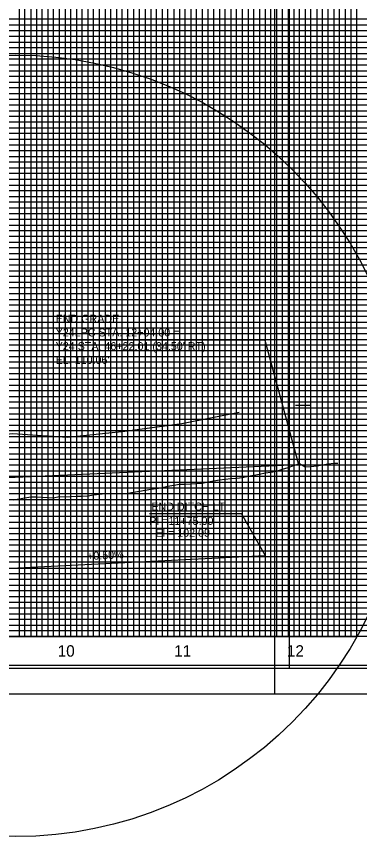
# Model space of a CAD drawing. Extents: x 2345490 to 2436403, y 465165 to 573888.
# Drawn here: x 2411853 to 2412153, y 523031 to 523748 of the extents above; entities that cross this region are included whole.
import ezdxf

# ---------------------------------------------------------------- set-up
doc = ezdxf.new("R2010")
doc.units = 0
for name, color, linetype in [('Old_Level_1', 7, 'Continuous'), ('Old_Level_18', 7, 'Continuous'), ('Old_Level_2', 7, 'Continuous'), ('Old_Level_3', 7, 'Continuous'), ('Old_Level_41', 7, 'Continuous'), ('Old_Level_42', 7, 'Continuous'), ('Old_Level_43', 7, 'Continuous'), ('Old_Level_50', 7, 'Continuous'), ('Old_Level_51', 7, 'Continuous'), ('Old_Level_52', 7, 'Continuous'), ('Old_Level_62', 7, 'Continuous'), ('Old_Level_63', 7, 'Continuous')]:
    doc.layers.add(name, color=color, linetype=linetype)

msp = doc.modelspace()

# ---------------------------------------------------------------- linework, layer by layer
at = {"layer": 'Old_Level_1'}
for points in [[(2411895.325, 523328.29225), (2411900.325, 523328.49575), (2411905.325, 523328.69875), (2411910.325, 523328.87125), (2411915.325, 523329.16725), (2411920.325, 523329.85425), (2411925.325, 523330.543), (2411930.325, 523331.213), (2411935.325, 523331.354), (2411940.325, 523331.2915), (2411945.325, 523331.228), (2411950.325, 523331.56175), (2411955.325, 523332.40075), (2411960.325, 523333.241), (2411965.325, 523334.03725), (2411970.325, 523334.8165), (2411975.325, 523335.638), (2411980.325, 523336.543), (2411985.325, 523337.448), (2411990.325, 523338.33525), (2411995.325, 523339.20225), (2412000.325, 523339.4425), (2412005.325, 523339.68275), (2412010.325, 523339.923), (2412015.325, 523340.271), (2412020.325, 523341.2105), (2412025.325, 523342.15), (2412030.325, 523343.073), (2412035.325, 523343.60075), (2412040.325, 523344.1285), (2412045.325, 523344.5875), (2412050.325, 523345.18675), (2412055.325, 523346.1825), (2412060.325, 523347.17825), (2412065.325, 523348.20575), (2412070.325, 523349.26625), (2412075.325, 523349.8425), (2412080.325, 523350.6675), (2412085.325, 523352.345), (2412090.325, 523354.02275), (2412095.325, 523355.70025), (2412100.325, 523357.37775), (2412105.325, 523354.34175), (2412110.325, 523354.80325), (2412115.325, 523355.2685), (2412120.325, 523356.19275), (2412125.325, 523357.16025), (2412130.325, 523357.7015), (2412133.825, 523357.63775)], [(2411850.325, 523325.50025), (2411855.325, 523326.38825), (2411860.325, 523327.27725), (2411865.325, 523328.109), (2411870.325, 523328.1615), (2411875.325, 523327.913), (2411880.325, 523327.676), (2411885.325, 523327.45375), (2411890.325, 523328.479), (2411895.325, 523328.29225)]]:
    msp.add_lwpolyline(points, dxfattribs=at)
at = {"layer": 'Old_Level_18'}
msp.add_lwpolyline([(2412345.325, 524230.9495), (2410845.325, 524230.9495), (2410845.325, 523180.9495), (2412345.325, 523180.9495)], close=True, dxfattribs=at)
at = {"layer": 'Old_Level_2'}
for p, q in [((2412069.99075, 523465.271), (2411874.5425, 523465.271)), ((2412069.99075, 523465.271), (2412099.325, 523356.5495)), ((2411845.325, 523345.0245), (2412099.325, 523356.5495))]:
    msp.add_line(p, q, dxfattribs=at)
at = {"layer": 'Old_Level_3'}
for p, q in [((2412049.63511, 523313.40272), (2411969.08786, 523313.40272)), ((2412049.63511, 523313.40272), (2412070.325, 523276.8495)), ((2411800.325, 523263.4495), (2412070.325, 523276.8495))]:
    msp.add_line(p, q, dxfattribs=at)
at = {"layer": 'Old_Level_41'}
for p, q in [((2412096.825, 523408.4495), (2412109.325, 523408.4495)), ((2412345.325, 523205.9495), (2410845.325, 523205.9495))]:
    msp.add_line(p, q, dxfattribs=at)
for points in [[(2411870.325, 524230.9495), (2411870.325, 523205.9495), (2411920.325, 523205.9495), (2411920.325, 524230.9495)], [(2411895.325, 524230.9495), (2411895.325, 523205.9495), (2411945.325, 523205.9495), (2411945.325, 524230.9495)], [(2411970.325, 524230.9495), (2411970.325, 523205.9495), (2412020.325, 523205.9495), (2412020.325, 524230.9495)], [(2411995.325, 524230.9495), (2411995.325, 523205.9495), (2412045.325, 523205.9495), (2412045.325, 524230.9495)], [(2412070.325, 524230.9495), (2412070.325, 523205.9495), (2412120.325, 523205.9495), (2412120.325, 524230.9495)], [(2412095.325, 524230.9495), (2412095.325, 523205.9495), (2412145.325, 523205.9495), (2412145.325, 524230.9495)], [(2412345.325, 523730.9495), (2410845.325, 523730.9495), (2410845.325, 523680.9495), (2412345.325, 523680.9495)], [(2412345.325, 523630.9495), (2410845.325, 523630.9495), (2410845.325, 523580.9495), (2412345.325, 523580.9495)], [(2412345.325, 523555.9495), (2410845.325, 523555.9495), (2410845.325, 523605.9495), (2412345.325, 523605.9495)], [(2412345.325, 523530.9495), (2410845.325, 523530.9495), (2410845.325, 523480.9495), (2412345.325, 523480.9495)], [(2412345.325, 523455.9495), (2410845.325, 523455.9495), (2410845.325, 523505.9495), (2412345.325, 523505.9495)], [(2412345.325, 523430.9495), (2410845.325, 523430.9495), (2410845.325, 523380.9495), (2412345.325, 523380.9495)], [(2412345.325, 523330.9495), (2410845.325, 523330.9495), (2410845.325, 523280.9495), (2412345.325, 523280.9495)], [(2412345.325, 523255.9495), (2410845.325, 523255.9495), (2410845.325, 523305.9495), (2412345.325, 523305.9495)], [(2412345.325, 523230.9495), (2410845.325, 523230.9495)]]:
    msp.add_lwpolyline(points, dxfattribs=at)
at = {"layer": 'Old_Level_42'}
for points in [[(2412345.325, 523655.9495), (2410845.325, 523655.9495), (2410845.325, 523705.9495), (2412345.325, 523705.9495)], [(2412345.325, 523355.9495), (2410845.325, 523355.9495), (2410845.325, 523405.9495), (2412345.325, 523405.9495)]]:
    msp.add_lwpolyline(points, dxfattribs=at)
at = {"layer": 'Old_Level_43'}
for points in [[(2411855.325, 524230.9495), (2411855.325, 523205.9495), (2411860.325, 523205.9495), (2411860.325, 524230.9495)], [(2411865.325, 524230.9495), (2411865.325, 523205.9495), (2411875.325, 523205.9495), (2411875.325, 524230.9495)], [(2411880.325, 524230.9495), (2411880.325, 523205.9495), (2411885.325, 523205.9495), (2411885.325, 524230.9495)], [(2411890.325, 524230.9495), (2411890.325, 523205.9495), (2411900.325, 523205.9495), (2411900.325, 524230.9495)], [(2411905.325, 524230.9495), (2411905.325, 523205.9495), (2411910.325, 523205.9495), (2411910.325, 524230.9495)], [(2411915.325, 524230.9495), (2411915.325, 523205.9495)], [(2411915.325, 523205.9495), (2411925.325, 523205.9495), (2411925.325, 524230.9495)], [(2411930.325, 524230.9495), (2411930.325, 523205.9495), (2411935.325, 523205.9495), (2411935.325, 524230.9495)], [(2411940.325, 524230.9495), (2411940.325, 523205.9495), (2411950.325, 523205.9495), (2411950.325, 524230.9495)], [(2411955.325, 524230.9495), (2411955.325, 523205.9495), (2411960.325, 523205.9495), (2411960.325, 524230.9495)], [(2411965.325, 524230.9495), (2411965.325, 523205.9495), (2411975.325, 523205.9495), (2411975.325, 524230.9495)], [(2411980.325, 524230.9495), (2411980.325, 523205.9495), (2411985.325, 523205.9495), (2411985.325, 524230.9495)], [(2411990.325, 524230.9495), (2411990.325, 523205.9495), (2412000.325, 523205.9495), (2412000.325, 524230.9495)], [(2412005.325, 524230.9495), (2412005.325, 523205.9495), (2412010.325, 523205.9495), (2412010.325, 524230.9495)], [(2412015.325, 524230.9495), (2412015.325, 523205.9495), (2412025.325, 523205.9495), (2412025.325, 524230.9495)], [(2412030.325, 524230.9495), (2412030.325, 523205.9495), (2412035.325, 523205.9495), (2412035.325, 524230.9495)], [(2412040.325, 524230.9495), (2412040.325, 523205.9495), (2412050.325, 523205.9495), (2412050.325, 524230.9495)], [(2412055.325, 524230.9495), (2412055.325, 523205.9495), (2412060.325, 523205.9495), (2412060.325, 524230.9495)], [(2412065.325, 524230.9495), (2412065.325, 523205.9495), (2412075.325, 523205.9495), (2412075.325, 524230.9495)], [(2412080.325, 524230.9495), (2412080.325, 523205.9495), (2412085.325, 523205.9495), (2412085.325, 524230.9495)], [(2412090.325, 524230.9495), (2412090.325, 523205.9495), (2412100.325, 523205.9495), (2412100.325, 524230.9495)], [(2412105.325, 524230.9495), (2412105.325, 523205.9495), (2412110.325, 523205.9495), (2412110.325, 524230.9495)], [(2412115.325, 524230.9495), (2412115.325, 523205.9495), (2412125.325, 523205.9495), (2412125.325, 524230.9495)], [(2412130.325, 524230.9495), (2412130.325, 523205.9495), (2412135.325, 523205.9495), (2412135.325, 524230.9495)], [(2412140.325, 524230.9495), (2412140.325, 523205.9495), (2412150.325, 523205.9495), (2412150.325, 524093.3995)], [(2412295.325, 523745.9495), (2410895.325, 523745.9495), (2410895.325, 523740.9495), (2412295.325, 523740.9495)], [(2412295.325, 523735.9495), (2410895.325, 523735.9495), (2410895.325, 523725.9495), (2412295.325, 523725.9495)], [(2412295.325, 523720.9495), (2410895.325, 523720.9495), (2410895.325, 523715.9495), (2412295.325, 523715.9495)], [(2412295.325, 523710.9495), (2410895.325, 523710.9495)], [(2410895.325, 523700.9495), (2412295.325, 523700.9495)], [(2412295.325, 523695.9495), (2410895.325, 523695.9495), (2410895.325, 523690.9495), (2412295.325, 523690.9495)], [(2412295.325, 523685.9495), (2410895.325, 523685.9495), (2410895.325, 523675.9495), (2412295.325, 523675.9495)], [(2412295.325, 523670.9495), (2410895.325, 523670.9495), (2410895.325, 523665.9495), (2412295.325, 523665.9495)], [(2412295.325, 523660.9495), (2410895.325, 523660.9495), (2410895.325, 523650.9495), (2412295.325, 523650.9495)], [(2412295.325, 523645.9495), (2410895.325, 523645.9495), (2410895.325, 523640.9495), (2412295.325, 523640.9495)], [(2412295.325, 523635.9495), (2410895.325, 523635.9495), (2410895.325, 523625.9495), (2412295.325, 523625.9495)], [(2412295.325, 523620.9495), (2410895.325, 523620.9495), (2410895.325, 523615.9495), (2412295.325, 523615.9495)], [(2412295.325, 523610.9495), (2410895.325, 523610.9495), (2410895.325, 523600.9495), (2412295.325, 523600.9495)], [(2412295.325, 523595.9495), (2410895.325, 523595.9495), (2410895.325, 523590.9495), (2412295.325, 523590.9495)], [(2412295.325, 523585.9495), (2410895.325, 523585.9495), (2410895.325, 523575.9495), (2412295.325, 523575.9495)], [(2412295.325, 523570.9495), (2410895.325, 523570.9495), (2410895.325, 523565.9495), (2412295.325, 523565.9495)], [(2412295.325, 523560.9495), (2410895.325, 523560.9495), (2410895.325, 523550.9495), (2412295.325, 523550.9495)], [(2412295.325, 523545.9495), (2410895.325, 523545.9495), (2410895.325, 523540.9495), (2412295.325, 523540.9495)], [(2412295.325, 523535.9495), (2410895.325, 523535.9495), (2410895.325, 523525.9495), (2412295.325, 523525.9495)], [(2412295.325, 523520.9495), (2410895.325, 523520.9495), (2410895.325, 523515.9495), (2412295.325, 523515.9495)], [(2412295.325, 523510.9495), (2410895.325, 523510.9495), (2410895.325, 523500.9495), (2412295.325, 523500.9495)], [(2412295.325, 523495.9495), (2410895.325, 523495.9495), (2410895.325, 523490.9495), (2412295.325, 523490.9495)], [(2412295.325, 523485.9495), (2410895.325, 523485.9495), (2410895.325, 523475.9495), (2412295.325, 523475.9495)], [(2412295.325, 523470.9495), (2410895.325, 523470.9495), (2410895.325, 523465.9495), (2412295.325, 523465.9495)], [(2412295.325, 523460.9495), (2410895.325, 523460.9495), (2410895.325, 523450.9495), (2412295.325, 523450.9495)], [(2412295.325, 523445.9495), (2410895.325, 523445.9495), (2410895.325, 523440.9495), (2412295.325, 523440.9495)], [(2412295.325, 523435.9495), (2410895.325, 523435.9495), (2410895.325, 523425.9495), (2412295.325, 523425.9495)], [(2412295.325, 523420.9495), (2410895.325, 523420.9495), (2410895.325, 523415.9495), (2412295.325, 523415.9495)], [(2412295.325, 523410.9495), (2410895.325, 523410.9495)], [(2410895.325, 523400.9495), (2412295.325, 523400.9495)], [(2412295.325, 523395.9495), (2410895.325, 523395.9495), (2410895.325, 523390.9495), (2412295.325, 523390.9495)], [(2412295.325, 523385.9495), (2410895.325, 523385.9495)], [(2410895.325, 523375.9495), (2412295.325, 523375.9495)], [(2412295.325, 523370.9495), (2410895.325, 523370.9495), (2410895.325, 523365.9495), (2412295.325, 523365.9495)], [(2412295.325, 523360.9495), (2410895.325, 523360.9495), (2410895.325, 523350.9495), (2412295.325, 523350.9495)], [(2412295.325, 523345.9495), (2410895.325, 523345.9495), (2410895.325, 523340.9495), (2412295.325, 523340.9495)], [(2412295.325, 523335.9495), (2410895.325, 523335.9495), (2410895.325, 523325.9495), (2412295.325, 523325.9495)], [(2412295.325, 523320.9495), (2410895.325, 523320.9495), (2410895.325, 523315.9495), (2412295.325, 523315.9495)], [(2412295.325, 523310.9495), (2410895.325, 523310.9495), (2410895.325, 523300.9495), (2412295.325, 523300.9495)], [(2412295.325, 523295.9495), (2410895.325, 523295.9495), (2410895.325, 523290.9495), (2412295.325, 523290.9495)], [(2412295.325, 523285.9495), (2410895.325, 523285.9495), (2410895.325, 523275.9495), (2412295.325, 523275.9495)], [(2412295.325, 523270.9495), (2410895.325, 523270.9495), (2410895.325, 523265.9495), (2412295.325, 523265.9495)], [(2412295.325, 523260.9495), (2410895.325, 523260.9495), (2410895.325, 523250.9495), (2412295.325, 523250.9495)], [(2412295.325, 523245.9495), (2410895.325, 523245.9495), (2410895.325, 523240.9495), (2412295.325, 523240.9495)], [(2412295.325, 523235.9495), (2410895.325, 523235.9495), (2410895.325, 523225.9495), (2412295.325, 523225.9495)], [(2412295.325, 523220.9495), (2410895.325, 523220.9495), (2410895.325, 523215.9495), (2412295.325, 523215.9495)], [(2412295.325, 523210.9495), (2410895.325, 523210.9495)]]:
    msp.add_lwpolyline(points, dxfattribs=at)
at = {"layer": 'Old_Level_50'}
msp.add_line((2412078.325, 523155.9495), (2412078.325, 523155.9495), dxfattribs=at)
for points in [[(2412357.825, 524233.4995), (2410691.325, 524233.4995), (2410691.325, 523178.3995), (2412357.825, 523178.3995)], [(2413757.825, 524233.4995), (2412091.325, 524233.4995), (2412091.325, 523178.3995), (2413757.825, 523178.3995)]]:
    msp.add_lwpolyline(points, close=True, dxfattribs=at)
at = {"layer": 'Old_Level_51'}
for points in [[(2412362.325, 524255.9495), (2410678.325, 524255.9495), (2410678.325, 523155.9495), (2412362.325, 523155.9495)], [(2413762.325, 524255.9495), (2412078.325, 524255.9495), (2412078.325, 523155.9495), (2413762.325, 523155.9495)]]:
    msp.add_lwpolyline(points, close=True, dxfattribs=at)
at = {"layer": 'Old_Level_52'}
msp.add_line((2412091.325, 523178.3995), (2412091.325, 523178.3995), dxfattribs=at)
at = {"layer": 'Old_Level_62'}
msp.add_lwpolyline([(2411670.325, 523358.2495), (2411705.245, 523379.1495), (2411751.605, 523384.8495), (2411802.195, 523378.2495), (2411849.335, 523383.5495), (2411897.465, 523380.3495), (2411947.495, 523385.7495), (2411997.495, 523392.4495), (2412047.495, 523402.3495)], dxfattribs=at)
msp.add_circle((2411852.2258, 523372.82877), 341.77216, dxfattribs=at)
at = {"layer": 'Old_Level_63'}
msp.add_line((2410895.325, 523205.9495), (2412133.8245, 523205.9495), dxfattribs=at)

# ---------------------------------------------------------------- texts
at = {"layer": 'Old_Level_2'}
for s, height, p in [('END GRADE', 7.000001, (2411887.121, 523480.519)), ('Y24LPC STA. 12+04.00 =', 7.0000005, (2411887.121, 523468.519)), ("Y24 STA. 46+22.01 (34.50' RT)", 7.0000005, (2411887.121, 523456.519)), ("EL. 110.06'", 7.0000005, (2411887.121, 523444.519))]:
    msp.add_text(s, height=height, dxfattribs=at).set_placement(p)
at = {"layer": 'Old_Level_3'}
for s, height, rotation, p in [('END DITCH LT', 7.0000005, 360, (2411970.79257, 523316.20041)), ('PI =11+75.00', 7.0000005, 360, (2411968.85241, 523303.70337)), ('El = 102.09', 7.0000005, 360, (2411974.41452, 523293.3373)), ('+0.50%', 7.000001, 2.84123527, (2411914.74421, 523272.86832))]:
    msp.add_text(s, height=height, rotation=rotation, dxfattribs=at).set_placement(p)
at = {"layer": 'Old_Level_62'}
for s, p in [('10', (2411888.9085, 523188.4495)), ('11', (2411990.748, 523188.4495)), ('12', (2412089.29625, 523188.4495))]:
    msp.add_text(s, height=10.000001, dxfattribs=at).set_placement(p)

doc.saveas('drawing.dxf')
